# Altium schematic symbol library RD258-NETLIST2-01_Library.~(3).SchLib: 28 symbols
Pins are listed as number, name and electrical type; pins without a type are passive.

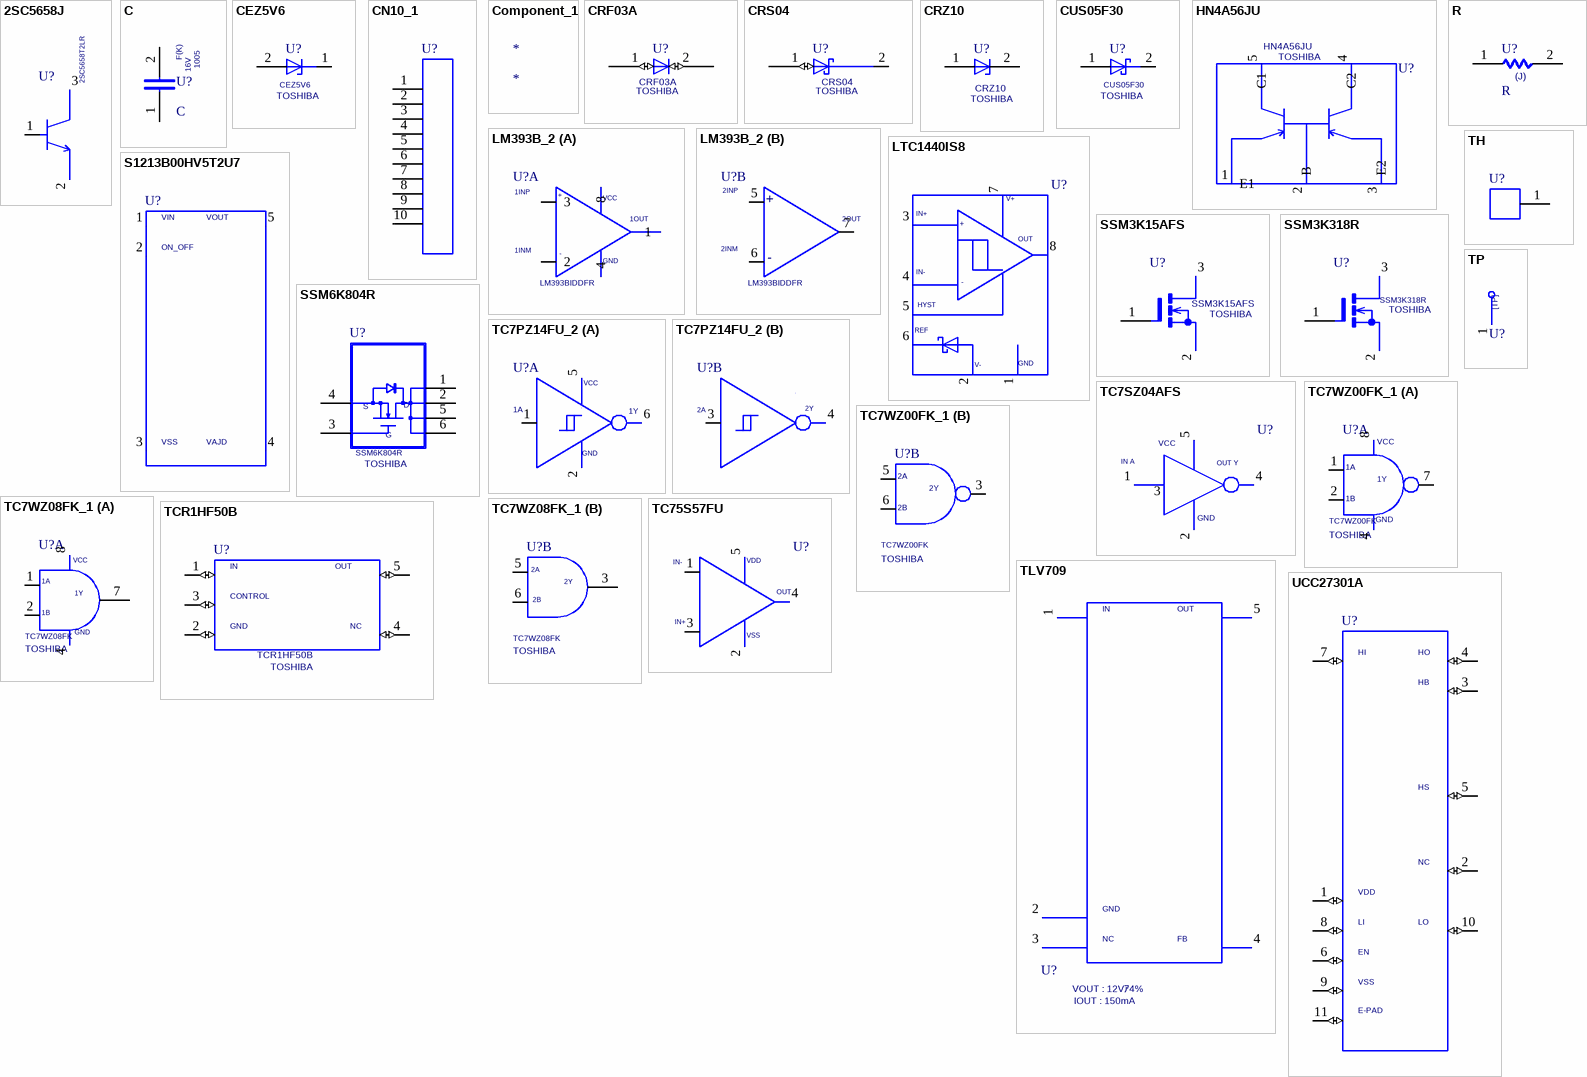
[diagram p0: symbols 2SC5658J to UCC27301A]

## 2SC5658J
designator U?  VAL1: 2SC5658T2LR  (hidden comment: 2SC5658J)
TIME: 09:39:04; UPDATEUSER: 19910145; UPDATETIME: 15:12:10; SAVECOUNT: 8; VENDOR: ROHM; SAVEAREA0: -6194,-158,18648,15662; PSPICETEMPLATE: X^@REFDES %C %B %E @MODEL; ORIGINALSYMBOLORIGIN: (0,0); Altium-Right: 20; Altium-Bottom: 80
simulation model 2SC5658J
pins: 1 B, 2 E, 3 C

## C
designator U?  VAL1: F(K)ODE: 1005  VOLTAGE: 16V  (hidden comment: C)
TIME: 08:48:12; UPDATEUSER: HP_Z8_KEYSHOT; SAVECOUNT: 2; TC1: 0; PSPICETEMPLATE: C^@REFDES %1 %2 ?TOLERANCE¦C^@REFDES¦ @VALUE ?IC/IC=@IC/ TC=@TC1,@TC2 ?TOLERANCE¦\n.model C^@REFDES CAP C=1 DEV=@TOLERANCE% TC1=@TC1 TC2=@TC2 VC1=@VC1 VC2=@VC2¦; ORIGINALSYMBOLORIGIN: (0,0); Altium-Right: 20; Altium-Bottom: 10
simulation model C
pins: 1, 2

## CEZ5V6
designator U?  VENDOR: TOSHIBA  (hidden comment: CEZ5V6)
TIME: 14:49:55; UPDATEUSER: fukuda-y; UPDATETIME: 08:16:22; SAVECOUNT: 9; SAVEAREA0: -4630,-153,17114,13055; PSPICETEMPLATE: X^@REFDES %C %A @MODEL; ORIGINALSYMBOLORIGIN: (0,0); Altium-Right: 20
simulation model CEZ5V6
pins: 1 C, 2 A

## CN10_1
designator U?, comment CN9_2  (value not drawn)
TIME: 08:48:13; UPDATEUSER: t5459927; UPDATETIME: 15:38:59; SAVECOUNT: 3; PSPICETEMPLATE: X^@REFDES %1 %2 %3 %4 %5 %6 %7 %8 %9 %10 %M1 %M2 @MODEL; COMP: CN9_1; USER_VALUE: XG4A-1031; OriginalSymbolOrigin: (0,0); Altium-Right: 20; Altium-Bottom: 130
simulation model CN10_1
pins: 1, 2, 3, 4, 5, 6, 7, 8, 9, 10

## Component_1
designator *

## CRF03A
designator U?  VENDOR: TOSHIBA  (hidden comment: CRF03A)
TIME: 08:48:14; UPDATEUSER: HP_Z8_KEYSHOT; SAVECOUNT: 2; PSPICETEMPLATE: X^@REFDES %A %C @MODEL; OriginalSymbolOrigin: (0,0); Altium-Right: 10; Altium-Bottom: 20
simulation model CRF03A
pins: 1 A (io), 2 C (io)

## CRS04
designator U?  VENDOR: TOSHIBA  (hidden comment: CRS04)
TIME: 08:48:14; UPDATEUSER: HP_Z8_KEYSHOT; SAVECOUNT: 2; PSPICETEMPLATE: X^@REFDES %A %C @MODEL; OriginalSymbolOrigin: (0,0); Altium-Right: 40; Altium-Bottom: 20
simulation model CRS04
pins: 1 A (io), 2 C (io)

## CRZ10
designator U?  VENDOR: TOSHIBA  (hidden comment: CRZ10)
TIME: 14:49:55; UPDATEUSER: fukuda-y; UPDATETIME: 08:18:42; SAVECOUNT: 6; SAVEAREA0: -4630,-153,17114,13055; PSPICETEMPLATE: X^@REFDES %A %C @MODEL; ORIGINALSYMBOLORIGIN: (0,0); Altium-Right: 10; Altium-Bottom: 20
simulation model CRZ10
pins: 1 A, 2 C

## CUS05F30
designator U?  VENDOR: TOSHIBA  (hidden comment: CUS05F30)
TIME: 14:49:55; UPDATEUSER: fukuda-y; UPDATETIME: 08:16:22; SAVECOUNT: 9; SAVEAREA0: -4630,-153,17114,13055; PSPICETEMPLATE: X^@REFDES %A %C @MODEL; ORIGINALSYMBOLORIGIN: (0,0); Altium-Right: 20
simulation model CUS05F30
pins: 1 A, 2 C

## HN4A56JU
designator U?  VENDOR: TOSHIBA  (hidden comment: HN4A56JU)
TIME: 08:48:13; UPDATEUSER: HP_Z8_KEYSHOT; SAVECOUNT: 2; PSPICETEMPLATE: X^@REFDES %B1 %E %B2 %C2 %C1 @MODEL; OriginalSymbolOrigin: (0,0); Altium-Right: 120; Altium-Bottom: 80
simulation model HN4A56JU
pins: 1 E1 (io), 2 B (io), 3 E2 (io), 4 C2 (io), 5 C1 (io)

## LM393B_2
designator U?  VAL1: LM393BIDDFR  (hidden comment: LM393B_2)
TIME: 08:48:12; UPDATEUSER: t5459927; UPDATETIME: 19:15:42; SAVECOUNT: 5; SPLIT_INST: TRUE; PSPICETEMPLATE: X^@REFDES %INN %VSS %INP %OUT %VDD @MODEL; VENDOR: TI; SWAP_INFO: (S1+S2); OriginalSymbolOrigin: (2540,0); Altium-Right: 70; Altium-Bottom: 60; Altium-Right1: 50
simulation model LM393B_2
part A pins: 1 (io), 2 (io), 3 (io), 4 (io), 8 (io)
part B pins: 5 (io), 6 (io), 7 (io)

## LTC1440IS8
designator U?  (value not drawn)
TIME: 08:48:16; UPDATEUSER: t5459927; UPDATETIME: 17:22:21; SAVECOUNT: 4; PSPICETEMPLATE: X^@REFDES %GND %V- %IN+ %IN- %HYST %REF %V+ %OUT @MODEL; OriginalSymbolOrigin: (0,0); Altium-Right: 90; Altium-Bottom: 120
simulation model LTC1440IS8
pins: 1 GND (io), 2 V- (io), 3 IN+ (io), 4 IN- (io), 5 HYST (io), 6 REF (io), 7 V+ (io), 8 OUT (io)

## R
designator U?  VAL1: (J)  (hidden comment: R)
TIME: 08:48:13; UPDATEUSER: HP_Z8_KEYSHOT; SAVECOUNT: 2; VAL2: 0.125; TC1: 0; PSPICETEMPLATE: R^@REFDES %1 %2 ?TOLERANCE¦R^@REFDES¦ @VALUE TC=@TC1,@TC2 ?TOLERANCE¦\n.model R^@REFDES RES R=1 DEV=@TOLERANCE% TC1=@TC1 TC2=@TC2¦; ORIGINALSYMBOLORIGIN: (0,0); Altium-Right: 20
simulation model R
pins: 1, 2

## S1213B00HV5T2U7
designator U?  (value not drawn)
TIME: 08:48:13; UPDATEUSER: t5459927; UPDATETIME: 09:48:38; SAVECOUNT: 7; PSPICETEMPLATE: X^@REFDES %ADJUST %OUTPUT %INPUT @MODEL; OriginalSymbolOrigin: (0,0); Altium-Right: 80; Altium-Bottom: 170
simulation model S1213B00HV5T2U7
pins: 1 (in), 2 (in), 3 (in), 4 (io), 5 (out)

## SSM3K15AFS
designator U?  VENDOR: TOSHIBA  (hidden comment: SSM3K15AFS)
TIME: 08:48:15; UPDATEUSER: HP_Z8_KEYSHOT; SAVECOUNT: 2; ORIGINALSYMBOLORIGIN: (0,0); PSPICETEMPLATE: X^@REFDES %D %G %S @MODEL; Altium-Right: 30; Altium-Bottom: 70
simulation model SSM3K15AFS
pins: 1 G, 2 S, 3 D

## SSM3K318R
designator U?  VENDOR: TOSHIBA  (hidden comment: SSM3K318R)
TIME: 08:48:16; UPDATEUSER: HP_Z8_KEYSHOT; SAVECOUNT: 2; ORIGINALSYMBOLORIGIN: (0,0); PSPICETEMPLATE: X^@REFDES %D %G %S @MODEL; Altium-Right: 30; Altium-Bottom: 70
simulation model SSM3K318R
pins: 1 G, 2 S, 3 D

## SSM6K804R
designator U?  VENDOR: TOSHIBA  (hidden comment: SSM6K804R)
TIME: 08:48:15; UPDATEUSER: HP_Z8_KEYSHOT; SAVECOUNT: 14; SAVEAREA0: -7120,-295,29516,23636; ORIGINALSYMBOLORIGIN: (0,0); PSPICETEMPLATE: X^@REFDES %1 %2 %3 %4 %5 %6 @MODEL; Altium-Right: 50; Altium-Bottom: 70
simulation model SSM6K804R
pins: 1, 2, 3, 4, 5, 6

## TC7PZ14FU_2
designator U?, comment TC7PZ17FU  (value not drawn)
TIME: 11:55:01; UPDATEUSER: t5459927; UPDATETIME: 19:09:34; SAVECOUNT: 7; SPLIT_INST: TRUE; PSPICETEMPLATE: X^@REFDES %1A %GND %2A %2Y %VCC %1Y @MODEL; COMP: TC7PZ17FU_2; VENDOR: TOSHIBA; SWAP_INFO: (S1+S2); OriginalSymbolOrigin: (5080,15240); Altium-Right: 70; Altium-Bottom: 60
simulation model TC7PZ14FU_2
part A pins: 1 (io), 2 (io), 5 (io), 6 (io)
part B pins: 3 (io), 4 (io)

## TC7SZ04AFS
designator U?  (value not drawn)
TIME: 11:55:02; UPDATEUSER: t5459927; UPDATETIME: 19:30:29; SAVECOUNT: 6; VENDOR: TOSHIBA; PSPICETEMPLATE: X^@REFDES %INA %GND %NC %OUTY %VCC @MODEL; OriginalSymbolOrigin: (0,-5080); Altium-Right: 80; Altium-Bottom: 60
simulation model TC7SZ04AFS
pins: 1 (io), 2 (io), 3 (io), 4 (io), 5 (io)

## TC7WZ00FK_1
designator U?, comment TC7WZ00FK  VENDOR: TOSHIBA
TIME: 08:52:39; UPDATEUSER: sptcae09; UPDATETIME: 16:09:46; SAVECOUNT: 9; SWAP_INFO: (S1+S2); COMP: TC7WZ00FK_2; ORDER: $pOrder; SPLIT_INST: TRUE; ・: 20mA; USER_VALUE: TC7W00FK; PSPICETEMPLATE: X^@REFDES %1A %1B %2Y %GND %2A %2B %1Y %VCC @MODEL; DESCRIPTION-A: NAND 2ch Logic; ORIGINALSYMBOLORIGIN: (2540,-2540); Altium-Right: 50; Altium-Bottom: 60; Altium-Bottom1: 40
simulation model TC7WZ00FK_1
part A pins: 1, 2, 4, 7, 8
part B pins: 3 2Y, 5 2A, 6 2B

## TC7WZ08FK_1
designator U?, comment TC7WZ08FK  VENDOR: TOSHIBA
TIME: 08:52:39; UPDATEUSER: sptcae09; UPDATETIME: 16:09:46; SAVECOUNT: 9; SWAP_INFO: (S1+S2); COMP: TC7WZ08FK_2; ORDER: $pOrder; SPLIT_INST: TRUE; ・: 20mA; USER_VALUE: TC7W00FK; PSPICETEMPLATE: X^@REFDES %1A %1B %2Y %GND %2A %2B %1Y %VCC @MODEL; DESCRIPTION-A: NAND 2ch Logic; ORIGINALSYMBOLORIGIN: (2540,-2540); Altium-Right: 40; Altium-Bottom: 60
simulation model TC7WZ08FK_1
part A pins: 1, 2, 4, 7, 8
part B pins: 3, 5, 6

## TC75S57FU
designator U?  (value not drawn)
TIME: 08:48:15; UPDATEUSER: t5459927; UPDATETIME: 11:03:38; SAVECOUNT: 3; VENDOR: TOSHIBA; PSPICETEMPLATE: X^@REFDES %INN %VSS %INP %OUT %VDD @MODEL; OriginalSymbolOrigin: (2540,0); Altium-Right: 60
simulation model TC75S57FU
pins: 1 (io), 2 (io), 3 (io), 4 (io), 5 (io)

## TCR1HF50B
designator U?  VENDOR: TOSHIBA
TIME: 11:54:59; UPDATEUSER: t5459927; UPDATETIME: 10:27:35; SAVECOUNT: 4; PSPICETEMPLATE: X^@REFDES %IN %GND %CONTROL %NC %OUT @MODEL; OriginalSymbolOrigin: (-2540,0); Altium-Right: 110; Altium-Bottom: 60
simulation model TCR1HF50B
pins: 1 (io), 2 (io), 3 (io), 4 (io), 5 (io)

## TH
designator U?  (value not drawn)
TIME: 18:11:32; UPDATEUSER: w20165dm; SAVECOUNT: 1; PSPICETEMPLATE: X^@REFDES %1 @MODEL; ORIGINALSYMBOLORIGIN: (0,0); Altium-Right: 20
simulation model TH
pins: 1

## TLV709
designator U?  NC: VOUT : 12Vｱ4%  CLASS: IOUT : 150mA  (hidden comment: TLV709)
TIME: 08:48:16; UPDATEUSER: t5459927; UPDATETIME: 10:01:49; SAVECOUNT: 5; PSPICETEMPLATE: X^@REFDES %IN %GND %NC %FB %OUT @MODEL; VAL1: TLV709A01DBVR; OriginalSymbolOrigin: (0,0); Altium-Right: 140; Altium-Bottom: 240
simulation model TLV709
pins: 1 (io), 2 (io), 3 (io), 4 (io), 5 (io)

## TP
designator U?  (value not drawn)
TIME: 16:12:21; UPDATEUSER: fukuda-y; UPDATETIME: 16:18:11; SAVECOUNT: 2; SAVEAREA0: -242,-92,12810,7836; ORIGINALSYMBOLORIGIN: (0,0); Altium-Right: 20; Altium-Bottom: 30
pins: 1

## UCC27301A
designator U?  (value not drawn)
TIME: 08:48:14; UPDATEUSER: t5459927; UPDATETIME: 20:55:41; SAVECOUNT: 11; VAL1: UCC27301ADRCR; PSPICETEMPLATE: X^@REFDES %VDD %NC %HB %HO %HS %EN %HI %LI %VSS %LO %THERMAL_PAD @MODEL; OriginalSymbolOrigin: (5080,60960); Altium-Right: 70; Altium-Bottom: 280
simulation model UCC27301A
pins: 1 (io), 2 (io), 3 (io), 4 (io), 5 (io), 6 (io), 7 (io), 8 (io), 9 (io), 10 (io), 11 (io)

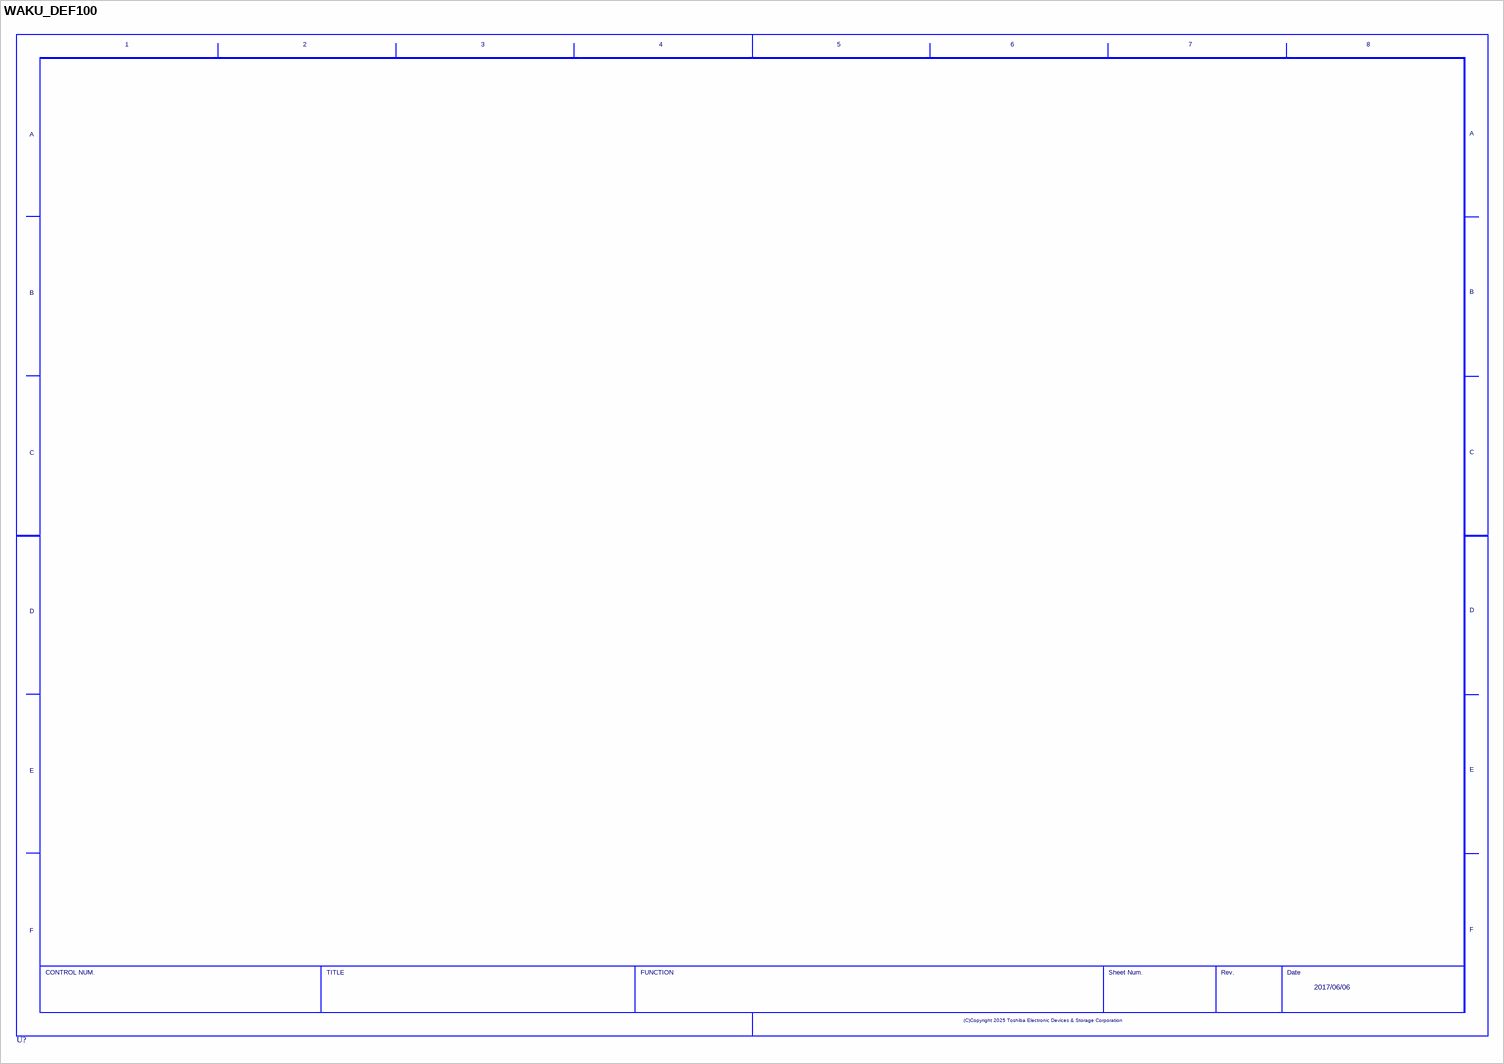
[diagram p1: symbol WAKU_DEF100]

## WAKU_DEF100
designator U?  DATE: 2017/06/06  (hidden comment: WAKU_DEF100)
PLOTTIME: HH:MM; SAVEAREA0: -63393,-16950,474261,314592; TIME: 14:30:25; UPDATEUSER: t5459927; UPDATETIME: 16:48:10; SAVECOUNT: 4; OriginalSymbolOrigin: (10160,284480); Altium-Right: 1570; Altium-Bottom: 1070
